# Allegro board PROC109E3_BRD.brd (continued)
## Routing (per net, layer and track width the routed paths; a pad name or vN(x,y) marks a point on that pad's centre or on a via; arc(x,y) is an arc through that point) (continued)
VBAT_XDS: length 4.1
  BOTTOM w0.178: 18.11,30.69 U37.68
  BOTTOM w0.33: 18.11,30.69 17.42,30 C208.1 R249.2
VBUS_DETECT: length 1.7
  TOP w0.135: R113.1 14.12,28.19 U20.4
VBUS_TYPEC: length 6.9
  TOP w0.254: J10.B4 19.77,16.49 J10.A9 19.77,18.71 v1(19.61,18.87) ; C70.1 20.43,19.81 ; J10.B9 17.27,16.49 J10.A4 17.27,18.5 v1(16.73,19.05)
  BOTTOM w0.381: J10.B4 19.72,16.97 ; J10.B9 17.32,16.97
  vias: v1(15.46,20.32) v1(15.46,19.05) v1(16.48,20.35) v1(19.68,23.88) v1(19.68,22.61) v1(19.84,21.59) v1(21.34,22.61)
VBUS_XDS_USB: length 43.5
  TOP w0.203: U24.10 U24.1
  TOP w0.254: 9.73,23.39 9.49,23.16 U24.10 ; v1(9.14,33.12) 8.06,32.04 2.58,32.04 TP27.1
  TOP w0.381: 6.81,22.71 6.48,22.38 J20.1
  BOTTOM w0.33: U38.6 11.57,32.65 ; 10.16,32.51 11.32,31.35 U38.4
  BOTTOM w0.381: R222.2 R219.1
  BOTTOM w0.635: 15.49,43.41 R222.2
  BOTTOM w0.762: 15.49,43.41 14.07,41.99 10.77,41.99 9.37,40.59 9.37,36.68 10.16,35.89 10.16,34.14 v1(9.14,33.12) 9.14,31.37 11.15,29.36 11.15,25.63 v1(9.35,23.83) v1(8.08,23.83)
VCC3V3_TA: length 96.8
  TOP w0.178: 29.54,52.12 29.37,51.95 U4.2 v1(28.57,51.65)
  TOP w0.203: v1(5.08,41.96) 5.49,41.55 TP49.1
  TOP w0.33: U4.1 C5.1 v1(30.96,54.08)
  TOP w0.381: v1(10.4,54.99) v1(10.4,53.11) v1(10.4,51.23) v1(10.4,49.35) v1(10.4,47.47) ; v1(26.39,51.1) 26.39,50.33 R28.2 ; v1(26.37,48.06) 26.37,48.81 R34.2 ; U9.5 4.21,45.81 v1(3.94,46.08) ; U9.8 4.31,43.86 4.01,43.56 v1(4.01,42.6) 4.65,41.96 v1(5.08,41.96)
  TOP w0.508: R17.2 26.39,51.8 v1(26.39,51.1) ; R53.2 R67.2 R70.2 ; R34.2 R28.2
  L03_SIG1 w0.381: v1(4.01,42.6) 3.94,42.67 v1(3.94,46.08) 8.18,46.08 9.58,47.47 v1(10.4,47.47) ; v1(4.01,42.6) 4.45,42.6 v1(5.08,41.96) ; v1(4.01,42.6) 4.01,36.86 v1(6.55,34.32) ; v1(28.57,51.65) 28.02,51.1 v1(26.39,51.1) 19.08,51.1 18.78,51.41 15.29,51.41 14.99,51.1 13.67,51.1 12.85,50.29 12.24,50.29 11.3,49.35 v1(10.4,49.35)
  L04_PWR1 w0.381: v1(7.49,26.03) v1(9.27,26.03) 9.27,27.23 v1(9.3,27.25)
  BOTTOM w0.254: U26.15 23.72,54.76 23.6,54.64 ; 23.75,54.36 23.85,54.26 U26.14 ; C146.1 7.57,35.81 ; C155.1 7.57,34.92
  BOTTOM w0.33: v1(22.53,53.29) 22.43,53.39 C85.1 ; 33.45,52.38 C88.1 U28.5
  BOTTOM w0.381: R209.2 v1(10.4,47.47) ; v1(9.3,27.25) 9.3,26.68 9.27,26.66 v1(9.27,26.03) 8.44,26.03 C243.1 8.33,26.03 v1(7.49,26.03)
  BOTTOM w0.508: R182.1 12.07,54.63 11.71,54.99 v1(10.4,54.99) R178.1 ; R191.2 24.94,49.49 v1(26.37,48.06) ; R202.2 12.07,48.99 11.71,49.35 v1(10.4,49.35) R197.2 ; R187.1 12.07,52.88 11.84,53.11 v1(10.4,53.11) R186.1 ; R196.2 12.07,50.79 11.63,51.23 v1(10.4,51.23) R189.2 ; 33.45,52.38 32.65,52.38 v1(30.96,54.08)
VCC3V3_XDS: length 93.9
  TOP w0.254: R109.2 v1(29.84,31.62) ; v1(27.28,30.1) 27.28,30.61 27.52,30.84 R108.2 ; v1(37.57,19.41) 37.57,18.01 TP35.1 ; C44.1 U16.7
  TOP w0.33: v1(67.85,24.67) 68.12,24.94 68.33,24.94 C60.1 68.44,24.8 68.44,24.49 68.09,24.14 U25.16 ; v1(25.07,34.14) C44.1
  TOP w0.381: v1(37.57,19.41) 40.28,22.12 40.28,32.05 38.86,33.48 ; R99.2 v1(22.05,33.12) ; 25.43,27.86 25.22,27.66 v1(25.22,26.42) ; R100.2 v1(23.52,33.12) ; R98.2 v1(20.5,33.12) ; R101.2 v1(24.99,33.12)
  L05_GND2 w0.381: v1(58.81,21.82) 59.29,22.3 66.52,22.3 67.85,23.64 v1(67.85,24.67)
  BOTTOM w0.178: U37.26 36.08,31.89 C180.1 ; U37.28 35.81,31.09 35.81,31.09 C191.1 ; v1(17.78,39.7) 17.78,39.66 17.96,39.49 U37.90 ; 27.1,44.45 U37.113 ; C121.1 36.67,39.49 U37.7 ; U37.51 25.9,26.9 ; v1(27.28,30.1) 27.55,29.82 27.55,28.95 27.5,28.9 U37.47 ; 30.71,26.77 30.7,26.78 U37.39 ; 35.94,39.19 35.84,39.09 U37.8 ; v1(30.7,42.24) 30.7,42.24 U37.122 ; U37.16 35.75,35.89 35.75,35.89 ; U42.8 C260.1 ; U37.79 17.94,35.09 ; 17.73,31.09 U37.69 ; U37.52 25.5,26.87 25.63,26.75 ; v1(22.02,44.73) 22.3,44.45 U37.101
  BOTTOM w0.254: U38.1 14.39,32.65 14.82,32.65 ; U45.16 36.23,19.02 36.44,18.81 C262.1 v1(37.57,19.41) ; v1(17.04,32.28) 17.04,31.78 17.73,31.09
  BOTTOM w0.33: v1(36.98,35.86) 36.98,35.87 C151.1 36.4,35.89 35.75,35.89 ; 38.44,40.06 v1(36.68,40.06) C121.1 ; v1(17.04,32.28) C181.1 C182.1 15.35,32.97 15.8,33.43 R246.1 ; 17.94,35.09 17.88,35.03 C154.1 16.47,35.03 v1(15.88,34.43) ; 27.1,44.45 26.95,44.6 C104.1 27.51,45.24 v1(27.51,45.24) ; 25.9,26.9 26.09,26.72 C242.1 25.5,26.14 v1(25.22,26.42) ; v1(31.62,26.72) 31.62,26.14 31.45,25.96 C240.1 30.71,26.77 ; v1(58.81,21.82) 58.87,21.88 64.9,21.88 65.2,21.58 C260.1
  BOTTOM w0.381: 38.44,40.06 38.7,40.06 R235.1 ; R249.1 15.35,28.47 15.73,28.09 v1(15.93,28.09)
  vias: v1(14.61,34.43) v1(14.61,33.16) v1(36.14,30.48) v1(36.17,32.72)
VCC_5V0_CAN: length 4.2
  TOP w0.203: v1(165.84,22.66) 164.92,22.66 TP50.1
  BOTTOM w0.254: v1(165.84,22.66) R270.2
  BOTTOM w0.33: U44.3 C257.1 R270.2
VDD_1V1: length 25.7
  TOP w0.254: v1(138.07,42.49) 137.52,42.49 C34.1 137.51,42.89 138.18,43.57 U7.39 ; v1(138.07,23.47) 138.06,23.45 C61.1 137.51,23.92 138.18,24.59 U19.39 ; U19.31 134.78,28.78 134.64,28.64 C56.1 133.98,29.18 133.99,29.18 v1(133.99,29.2) ; C17.1 v1(144.35,47.83) U7.6 ; C55.1 v1(144.35,28.78) U19.6 ; U7.31 134.78,47.83 134.64,47.69 C19.1 133.98,48.23 133.99,48.23 v1(133.99,48.25)
  TOP w0.381: TP30.1 125.19,28.46 v1(125.19,27.25)
  BOTTOM w0.229: 125.6,29.67 125.48,29.79 U39.10 ; 125.73,30.05 125.49,30.29 U39.9
  BOTTOM w0.254: v1(138.07,42.49) 138.02,42.44 C113.1 ; C97.1 133.96,48.23 v1(133.99,48.25)
  BOTTOM w0.33: C229.1 126.19,27.49 ; C96.1 144.34,47.83 v1(144.35,47.83) C17.1 ; C55.1 v1(144.35,28.78) 144.34,28.78 C217.1 ; v1(133.99,29.2) 133.98,29.19 C56.1 134,28.62 C228.1 ; v1(138.07,23.47) 138,23.39 C256.1 ; C98.1 133.96,46.62 C97.1
  BOTTOM w0.508: C222.1 125.7,28.63
  vias: v1(125.19,25.98) v1(126.46,25.98)
VDD_1V1_SS: length 1.7
  BOTTOM w0.203: C183.1 126.1,31.29 U39.7
VDD_1V8: length 84.1
  TOP w0.203: TP5.1 63.58,53.01 40.82,53.01 37.83,55.99 33.24,55.99 32.33,55.09 31.29,55.09 30.73,55.66 29.9,55.66 26.9,52.65 25.21,52.65 24.85,52.3 23.83,52.3 23.55,52.58 22.92,52.58 19.94,49.6 v1(19.94,47.93)
  TOP w0.254: C30.2 76.61,41.94 76.87,41.67 U11.5 ; v1(66.17,51.31) 66.17,50.93 R30.2 65.1,51.19 v1(65.1,51.32) 64.69,51.32 R29.2
  TOP w0.305: U18.F14 79.35,32.4 v2(79.35,32.84)
  TOP w0.33: v1(77.37,42.47) 77.37,42.49 77.04,42.82 C30.2
  TOP w0.381: v1(92.18,30.56) v1(92.99,30.56)
  L03_SIG1 w0.152: v2(79.35,32.84) 78.7,33.49 77.44,33.49 77.33,33.38
  L03_SIG1 w0.254: 77.33,33.38 73.11,33.38 72.71,33.78 71.35,33.78 68.88,31.32 v1(68.3,31.32)
  L03_SIG1 w0.381: v1(66.17,51.31) 65.11,51.31 v1(65.1,51.32)
  L04_PWR1 w0.254: v1(92.18,30.56) 92.04,30.69 92.04,33.94 91.31,34.67
  L04_PWR1 w0.508: v1(77.06,41.05) 77.06,42.16 v1(77.37,42.47)
  BOTTOM w0.135: v1(91.72,28.4) v1(92.99,28.4)
  BOTTOM w0.305: C162.1 78.63,33.36 78.63,33.36 79.15,32.84 v2(79.35,32.84)
  BOTTOM w0.381: R198.1 v1(19.94,47.93) ; FB1.1 77.37,43.22 v1(77.37,42.47) 78.09,41.74 FB2.1
  BOTTOM w0.508: FB2.1 77.14,41.12 v1(77.06,41.05)
  vias: v1(64.9,52.58) v1(66.17,52.58) v1(68.76,25.45)
VDD_1V8_CT: length 3.8
  BOTTOM w0.254: U27.5 17.74,57.82 18.71,58.79 C80.1
VDD_1V8_ENABLE: length 31.4
  TOP w0.254: U10.8 42.79,44.11 v1(42.55,43.87) 39.29,43.87 38.81,44.35 38.81,49.96 41.05,52.2 56.55,52.2 57.07,51.68 R31.1
  BOTTOM w0.381: R224.1 v1(42.55,43.87)
VDD_1V8_R: length 1
  TOP w0.33: 62.61,48.25 U5.1 ; C20.1 64.67,48.36
VDD_1V8_SENSE: length 5.9
  BOTTOM w0.135: U27.10 19.57,53.08 19.94,52.71 R198.2 R199.1
VDD_2V5: length 19.9
  TOP w0.254: C23.1 v1(144.35,46.33) U7.3 ; U19.9 v1(144.35,30.28) C53.1 ; C58.1 v1(144.35,27.28) U19.3 ; C11.1 v1(144.35,49.33) U7.9
  TOP w0.381: v1(125.24,37.97) 125.24,38.77 TP20.1 R81.2
  BOTTOM w0.229: 125.73,40.77 125.49,41.01 U33.9 ; U33.10 125.48,40.51 125.6,40.39
  BOTTOM w0.33: C231.1 144.32,27.25 v1(144.35,27.28) C58.1 144.95,26.78 145.03,26.7 C238.1 144.68,26.03 v1(144.32,25.68) ; C11.1 v1(144.35,49.33) ; C107.1 145.03,45.67 144.91,45.8 144.95,45.84 C23.1 v1(144.35,46.33) 143.8,46.33 C100.1 ; C53.1 v1(144.35,30.28) ; C130.1 126.28,38.21
  BOTTOM w0.381: C107.1 144.6,45.09 v1(144.22,44.7)
  BOTTOM w0.508: C125.1 125.71,39.35 125.7,39.34
  vias: v1(125.24,36.7) v1(126.46,36.7)
VDD_2V5_PG: length 21.5
  TOP w0.203: R81.1 v1(115.7,39.37)
  TOP w0.254: v1(121.34,41.35) 121.99,40.69 R81.1
  BOTTOM w0.203: U33.3 121.49,41.51 v1(121.34,41.35) ; U39.5 121.35,31.79 120.37,32.77 117.98,32.77 115.7,35.05 v1(115.7,39.37)
VDD_2V5_SS: length 1.7
  BOTTOM w0.203: C111.1 126.1,42.01 U33.7
VDD_CORE_0V85: length 122.9
  TOP w0.102: U18.J10 80.89,30.34 81.38,29.86
  TOP w0.152: U18.R12 83.89,31.38 83.41,31.86 ; U18.N10 82.89,30.29 v2(83.37,29.82) 83.89,30.35 U18.R10
  TOP w0.178: v2(80.41,31.9) 80.7,31.59 U18.J12
  TOP w0.254: U18.L9 v2(81.89,29.39) ; v1(57.76,32.38) 57.76,31.78 C49.1 ; v2(85.36,32.9) 85.39,32.94 U18.V16 ; C48.1 56.62,32.26 v1(56.49,32.38) ; TP23.1 56.49,36.58 v1(56.49,34.92)
  TOP w0.305: U18.R9 83.89,29.45 v2(83.94,29.41) 83.45,29.41 U18.P8 ; v2(80.41,29.84) 80.41,29.38 U18.H8 ; U18.F11 79.39,30.42 v2(79.41,30.4) 79.45,30.36 U18.G10 ; v2(81.39,29.84) 81.38,29.86 U18.J9 ; U18.J12 80.94,31.32 v2(81.4,31.32) 81.39,31.31 U18.K11 ; U18.H15 80.37,32.89 v2(79.87,32.89) ; U18.M8 82.85,29.36 v2(82.88,29.39) 82.88,29.85 U18.N9 ; U18.L13 81.5,31.86 v2(81.46,31.9) 81.39,31.97 U18.K14 ; v2(79.91,28.82) 79.89,28.8 U18.G6 U18.G5 ; v2(80.41,30.4) 80.45,30.36 U18.J10 ; U18.R13 83.41,31.86 v2(83.37,31.9) 83.39,31.93 U18.P14 ; v2(82.39,31.9) U18.M14
  TOP w0.508: C62.1 R130.1 v1(51.26,24.51) ; 55.46,32.26 55.08,32.64 R96.1 55.08,34.55 55.33,34.8
  L03_SIG1 w0.254: v1(56.49,34.92) 56.49,39.11 54.97,40.64 39.45,40.64 36.68,43.41 35.51,43.41 31.24,47.68 31.24,52.42 27.55,56.11 v1(23.22,56.11)
  L04_PWR1 w0.102: v2(83.37,31.9) 83.92,31.9 84.4,32.38
  L04_PWR1 w0.254: v1(79.35,22.56) 78.84,22.56 78.26,21.97 72.77,21.97 70.84,23.9 70.84,25.27 69.93,26.19 63.7,26.19 63.37,25.86 52.6,25.86 v1(51.26,24.51)
  L04_PWR1 w0.305: 84.4,32.38 84.73,32.38 85.25,32.9 v2(85.36,32.9)
  BOTTOM w0.254: C187.1 81.56,31.8 v2(81.46,31.9) 81.4,31.9 v2(81.4,31.32)
  BOTTOM w0.305: C211.1 83.84,29.31 v2(83.94,29.41) ; C211.1 83.32,29.77 v2(83.37,29.82) ; C211.1 82.97,29.31 v2(82.88,29.39) 82.8,29.31 C212.1 81.98,29.31 v2(81.89,29.39) ; v2(83.37,31.9) 83.26,31.8 C186.1 82.5,31.8 v2(82.39,31.9) 82.29,31.8 C187.1 ; v2(80.41,30.4) v2(80.41,29.84) 80.47,29.9 C200.1 ; v2(81.46,31.9) 81.36,31.8 C188.1 80.51,31.8 v2(80.41,31.9) ; C214.1 80.15,28.57 v2(79.91,28.82) 79.91,27.89 C227.1 ; C199.1 81.5,29.95 v2(81.39,29.84)
  BOTTOM w0.33: C227.1 79.67,27.89 79.65,27.88 79.65,27.88 79.36,27.59 79.36,27.58 79.2,27.42 79.2,27.15 ; C163.1 79.96,32.98 v2(79.87,32.89) ; v2(80.41,30.4) 80.35,30.34 C201.1 79.47,30.34 v2(79.41,30.4) ; v2(85.36,32.9) 85.36,33.01 C165.1
  BOTTOM w0.381: v1(74.8,35.76) 74.52,36.04 C136.1 74.52,36.47 v1(73.74,36.47) ; v1(79.35,22.56) 79.15,22.75 C255.1 79.91,23.29 v1(80.11,23.09)
  BOTTOM w0.508: v1(23.22,56.11) 22.61,56.72 R176.2 ; C234.1 79.2,27.15
  vias: v1(56.49,33.66) v1(57.76,34.92) v1(57.76,33.66) v1(59.03,34.92) v1(59.03,33.66) v1(59.03,32.38) v1(60.3,34.92) v1(60.3,33.66) v1(60.3,32.38) v1(76.2,35.94) v1(80.14,25.27) v1(80.06,24.28) v1(80.8,22.56)
VDD_CORE_0V85_EN: length 36.4
  TOP w0.254: R127.1 48.68,24.53 48.94,24.78 v1(48.94,25.25)
  TOP w0.381: U5.3 62.91,49.54 63.23,49.87 R29.1 v1(62.41,50.9)
  BOTTOM w0.203: v1(48.94,25.25) 48.94,28.13 49.99,29.18 49.99,31.62 60.19,41.82 60.19,49.7 61.39,50.9 v1(62.41,50.9)
VDD_CORE_0V85_FB: length 4.4
  TOP w0.254: C62.2 R130.2 R124.1 49.64,25.93 49.64,27.37 49.64,27.37 U21.2
VDD_CORE_0V85_H_SENSE: length 5.9
  TOP w0.135: v1(20.47,58.14) 21.3,58.14 R6.1
  BOTTOM w0.135: U27.6 19.5,55.08 19.68,55.26 19.68,57.35 v1(20.47,58.14) 21.28,58.14 R175.2
VDD_CORE_0V85_L_SENSE: length 5.1
  TOP w0.135: R6.2 20.82,57.06 v1(20.47,56.72)
  BOTTOM w0.135: U27.7 19.5,54.58 20.04,55.11 20.04,56.29 v1(20.47,56.72) R176.1
VDD_CORE_0V85_PG: length 62
  TOP w0.254: Q3.3 v1(3.01,32.83) ; R112.1 U21.8
  TOP w0.381: v1(42.8,31.37) 42.8,29.44 43.37,28.87 R112.1
  L03_SIG1 w0.381: v1(42.8,31.37) 41.22,31.37 38.57,34.02 38.57,39.89 36.82,41.64 32.27,41.64 31.5,40.87 27.37,40.87 26.97,41.26 21.53,41.26 21.24,40.98 15.39,40.98 15,41.37 12.72,41.37 7.11,35.76 7.11,33.9 6.6,33.4 3.59,33.4 v1(3.01,32.83)
VDD_CORE_0V85_R: length 3.8
  TOP w0.254: C50.1 53.32,31.73 53.85,32.26
  TOP w0.508: 53.85,32.26 54.1,32.51 R96.2 54.1,34.42 53.72,34.8
VDD_CORE_0V85_SW: length 4.8
  TOP w0.254: 50.56,30.27 50.56,30.14 50.14,29.71 U21.6
  TOP w0.762: 50.56,30.27 L2.1
VDDA_1P8_USB0: length 6.8
  TOP w0.152: U18.U15 84.89,32.79 v2(85.36,32.33)
  TOP w0.254: TP47.1 v1(92.53,33.73)
  BOTTOM w0.127: C177.1 86.69,32.3
  BOTTOM w0.152: v2(85.36,32.33) 85.73,31.95 86.35,31.95 86.69,32.3
  BOTTOM w0.254: FB5.2 90.56,32.57 91.24,33.25 91.62,33.25 92.1,33.73 v1(92.53,33.73)
  BOTTOM w0.33: C176.1 C177.1
VDDA_1V8: length 105.6
  TOP w0.254: TP40.1 34.14,56.69 v1(32.59,56.69)
  TOP w0.305: U18.F18 79.82,34.36 v2(79.85,34.33) ; v2(79.89,32.33) 79.93,32.36 U18.H14
  TOP w0.33: U1.5 31.91,57.94 32.57,57.28 C4.1 v1(32.59,56.69)
  TOP w0.381: R15.2 12.21,52.93 12.59,52.54 v1(12.82,52.54)
  L03_SIG1 w0.381: v1(12.82,52.54) 12.82,54.24 14.73,56.15 21.7,56.15 22.25,56.69 v1(32.59,56.69) 32.59,47.35 34.04,45.9 35.48,45.9 36.09,46.5 37.21,46.5 38.33,45.38 49.84,45.38 50.2,45.02 55.61,45.02 56.98,43.66 71.66,43.66 74.93,40.39 77.55,40.39 78.28,41.12 v1(80.59,41.12) 79.68,40.21 79.68,38.38 v1(79.96,38.1)
  L05_GND2 w0.203: v2(79.85,34.33) 79.85,33.88 80.27,33.46 80.27,32.71 v2(79.89,32.33)
  BOTTOM w0.305: v2(79.85,34.33) 79.69,34.33 79.05,34.97 79.05,35.14 78.7,35.48 C153.1
  BOTTOM w0.33: 79.33,37.81 78.7,37.19 C135.1 C144.1 C153.1 ; 79.4,39.2 C126.1
  BOTTOM w0.381: C126.1 79.33,37.81 79.32,37.81
  BOTTOM w0.508: v1(80.59,41.12) 79.7,41.12 FB2.2 79.69,40.22 79.71,40.21 79.33,39.83 C126.1
VDDA_3P3_USB0: length 12.8
  TOP w0.152: U18.U16 84.89,33.32 v2(84.42,32.85)
  TOP w0.254: v1(89.81,35.84) 90.22,35.84 TP45.1
  L03_SIG1 w0.254: v1(89.81,35.84) 88.9,35.84 86.4,33.34 84.97,33.34 84.48,32.85 v2(84.42,32.85)
  BOTTOM w0.152: C178.1 84.85,33.3 84.42,32.86 v2(84.42,32.85)
  BOTTOM w0.33: C157.1 87.27,34.75 87.59,35.06 C156.1
  BOTTOM w0.508: C156.1 88.84,35.06 89,34.9 FB4.2 89.65,35.67 v1(89.81,35.84)
VDDA_3V3: length 19.1
  TOP w0.102: v2(80.89,32.38) 81.12,32.6 81.13,32.6 U18.K15
  TOP w0.254: TP43.1 70.38,38.92 70.38,37.87 70.79,37.45 v1(70.79,37.44)
  L03_SIG1 w0.152: v1(70.79,37.44) 71.25,36.98 77.29,36.98 79.28,35 79.28,34.23 80.51,33 80.51,32.75 80.88,32.38 v2(80.89,32.38)
  BOTTOM w0.305: C174.1 80.6,32.38 v2(80.89,32.38)
  BOTTOM w0.33: FB3.2 C142.1
  BOTTOM w0.508: FB3.2 71.3,36.49 70.79,37 v1(70.79,37.44)
VDDA_ADC: length 18.9
  TOP w0.203: TP48.1 80.39,41.99 v1(80.39,42.62)
  TOP w0.305: v2(80.41,34.33) 80.41,33.88 U18.H17 U18.G17
  L03_SIG1 w0.381: v2(80.41,34.33) 80.47,34.33 80.9,34.76 80.9,35.63 81.11,35.84 81.11,38.88 80.79,39.2 80.79,39.94 81.45,40.6 81.45,41.56 v1(80.39,42.62)
  BOTTOM w0.203: v2(80.41,34.33) 80.74,34.66 80.74,35.3 80.7,35.34
  BOTTOM w0.254: C147.1 80.56,35.48 80.7,35.34
  BOTTOM w0.33: v1(80.39,42.62) 81.06,42.62 81.39,42.29 81.39,41.97 C116.1 ; C147.1 C148.1
  BOTTOM w0.508: v1(80.39,42.62) 80.24,42.47 79.61,42.47 79.31,42.77 FB1.2 C109.1
VDDA_PLL0: length 13.4
  TOP w0.254: TP41.1 90.22,27.13 v1(91.06,27.13)
  TOP w0.305: U18.N12 83.32,31.36 v2(83.37,31.32)
  L03_SIG1 w0.102: 86.39,30.76 85.75,30.76 85.54,30.55 85.2,30.55 84.84,30.91 83.77,30.91 v2(83.37,31.32)
  L03_SIG1 w0.254: 89.05,30.56 88.06,30.56 87.86,30.76 86.39,30.76
  L03_SIG1 w0.381: 89.05,30.56 v1(89.46,30.56) v1(90.3,30.56)
  BOTTOM w0.254: FB7.2 90.26,29.57 90.95,28.87 90.95,28.72 91.06,28.61 v1(91.06,27.13)
  BOTTOM w0.305: C185.1 v2(83.37,31.32)
  BOTTOM w0.33: C206.1 87.96,29.8 87.95,29.79 C204.1
VDDA_PLL1: length 12.8
  TOP w0.305: U18.G9 79.88,29.84 v2(79.39,29.84)
  TOP w0.381: v1(74.96,27.36) 73.99,26.39 TP44.1
  L03_SIG1 w0.254: v1(74.96,27.36) 77.44,29.84 v2(79.39,29.84)
  BOTTOM w0.254: v1(74.96,27.36) 74.41,26.84 74.41,26.78 74.02,26.38 C236.1 73.52,26.37 73.49,26.4 C241.1 72.17,26.4 72.09,26.31 FB9.2 ; C210.1 79.37,29.84 v2(79.39,29.84)
VDDA_PLL2: length 14.2
  TOP w0.254: TP46.1 72.62,31.22 v1(71.81,31.22)
  TOP w0.381: v2(79.42,31.32) 79.46,31.36 U18.G12
  L03_SIG1 w0.254: v2(79.42,31.32) 79.39,31.32 78.81,31.9 78.25,31.9 78.08,32.07 77.13,32.07 75.87,30.81 72.21,30.81 v1(71.81,31.22)
  BOTTOM w0.33: C194.1 73.76,30.7 73.31,31.15 C193.1 72.5,31.22 v1(71.81,31.22) 71.39,31.22 FB6.2
  BOTTOM w0.356: C184.1 78.87,31.52 79.07,31.32 v2(79.42,31.32)
VDDA_TEMP: length 19.2
  TOP w0.102: U18.G11 79.95,30.86 v2(80.41,31.32)
  TOP w0.254: U18.M11 v2(82.39,30.4) ; TP42.1 v1(71.88,29.34)
  L03_SIG1 w0.152: 77.55,31.71 78.01,31.71 78.25,31.47 78.54,31.47
  L03_SIG1 w0.254: 77.55,31.71 76.09,30.25 72.8,30.25 v1(71.88,29.34) ; v2(82.39,30.4) 81.91,30.89 80.84,30.89 v2(80.41,31.32) 79.98,30.89 79.12,30.89 78.54,31.47
  BOTTOM w0.254: v2(80.41,31.32) 80.37,31.32 80.06,31.62 C190.1
  BOTTOM w0.305: v2(82.39,30.4) 82.55,30.56 C198.1
  BOTTOM w0.33: C225.1 73.39,28.66 73.51,28.78 C224.1
  BOTTOM w0.508: C225.1 72.03,28.66 71.87,28.5 FB8.2
VDDC_1V2_XDS: length 37.8
  TOP w0.254: v1(18.06,37.29) 34.87,37.29 37.47,39.88 37.47,41.17 34.75,43.89 v1(33.86,43.89)
  BOTTOM w0.178: U37.87 18.16,38.29 ; U37.115 27.9,44.48
  BOTTOM w0.33: v1(18.06,37.29) 18.01,37.34 17.98,37.34 C132.1 17.82,38.29 18.16,38.29 ; v1(33.86,43.89) 33.86,44.44 33.14,45.15 C102.1 C105.1 28.1,44.67 27.9,44.48
VDDSHV_3V3: length 55.9
  TOP w0.152: 83.94,33.86 v2(84.39,33.4) ; v2(78.44,29.39) 78.89,29.85 U18.E9 ; v2(81.89,28.82) 82.35,28.36 U18.M6 ; v2(83.85,28.85) 83.85,28.82 U18.P6 ; 78.47,29.36 78.59,29.24 78.59,29.23 78.89,28.93 U18.E7 ; U18.U8 84.41,29.84 v2(84.36,29.84)
  TOP w0.254: v1(84.58,22.48) 84.58,23.09 TP52.1 ; U18.C13 78.33,32.3 78.39,32.3 ; U18.R17 83.94,33.86
  TOP w0.305: v2(82.88,32.9) 82.88,33.35 U18.N16 U18.N17 ; U18.L6 v2(81.89,28.82) ; U18.U8 U18.U7 ; U18.P5 U18.P6 ; v2(78.44,32.9) 78.48,32.86 U18.E15 ; U18.D13 78.39,32.3 v2(78.43,32.33) 78.45,32.36 U18.E14 ; U18.T8 84.39,29.6 84.36,29.63 v2(84.36,29.84) ; U18.T17 v2(84.39,33.4) ; U18.T11 U18.U11 84.89,31.27 v2(84.94,31.32) ; v2(78.44,29.39) 78.47,29.36 U18.E8
  L03_SIG1 w0.33: v1(84.3,38.2) 84.3,37.66 84.64,37.32 84.64,34.32 84.39,34.08 v2(84.39,33.4)
  L04_PWR1 w0.152: v2(84.36,29.84) 84.36,29.27 83.95,28.85 v2(83.85,28.85)
  L04_PWR1 w0.254: v2(84.36,29.84) 84.83,29.84 ; v2(84.39,33.4) 84.84,33.4
  BOTTOM w0.178: v2(83.85,28.85) 83.94,28.85 84.29,29.21 C213.1
  BOTTOM w0.254: C205.1 85.21,31.32 v2(84.94,31.32) ; 84.45,26.25 84.45,26.14 84.46,26.13 ; v2(81.89,28.82) 81.89,28.69 82.25,28.34 82.57,28.34 82.71,28.19 83.54,28.19
  BOTTOM w0.305: C175.1 82.69,33.1 v2(82.88,32.9) 82.88,33.36 83.25,33.73 84.07,33.73 v2(84.39,33.4) 84.39,34.1 C158.1 84.39,34.34 84.39,35.65 C145.1 ; C215.1 81.6,28.52 v2(81.89,28.82) ; C235.1 84.45,26.25 84.45,27.53 83.85,28.13 v2(83.85,28.85) ; v2(84.36,29.84) 85.16,29.84 85.17,29.85 85.27,29.85 C203.1 ; v2(78.44,29.39) 78.44,29.55 C202.1
  BOTTOM w0.33: C145.1 C140.1 ; C140.1 C133.1 84.61,37.89 v1(84.3,38.2) ; C140.1 C141.1 C134.1 84.21,38.2 v1(84.3,38.2) ; v1(84.3,38.2) v1(84.3,39.01)
  BOTTOM w0.381: v2(78.44,32.9) 78.43,32.89 v2(78.43,32.33) 77.53,32.33 77.01,32.85 C167.1
  BOTTOM w0.508: v1(84.58,22.48) 83.85,21.74 76.17,21.74 75.46,22.45 75.46,25.96 76.28,26.77
  vias: v1(85.6,22.48)
VDDSHV_SDIO: length 34.8
  TOP w0.305: v2(81.85,32.9) 81.89,32.95 U18.L16 U18.L17 ; U18.J17 80.94,33.82 v2(81.41,33.82)
  TOP w0.381: R19.2 89.05,50.41 88.67,50.79 v1(88.67,51.64) ; R21.2 93.29,50.41 v1(93.29,50.42)
  L03_SIG1 w0.254: v2(81.41,33.82) 81.41,33.35 v2(81.85,32.9)
  L04_PWR1 w0.381: v1(88.67,51.64) 86.16,51.64 81.38,46.86 v1(81.38,39.67)
  BOTTOM w0.203: C143.1 81.36,35.41 81.05,35.1 81.05,34.54 C160.1
  BOTTOM w0.33: C160.1 81.37,34.21 81.37,34.13 81.41,34.1 v2(81.41,33.82) 81.39,33.79 C172.1 ; v1(81.38,39.67) 81.38,38.62 80.54,37.78 80.54,36.69 C143.1
  BOTTOM w0.381: v1(88.67,51.64) 88.67,51.59 88.65,51.57 R194.2 R193.2 R192.2 92.75,50.96 v1(93.29,50.42)
BOARD_POWER_EN: length 5.2
  TOP w0.254: R84.2 R85.1 42.3,39.53 43.29,40.52 43.29,41.87 43.43,42 U10.1
BOOTMODE0: length 2.1
  TOP w0.135: R39.1 87.12,47.21 v1(87.12,46.51) 87.12,45.83 R55.2
  BOTTOM w0.135: v1(87.12,46.51) 87.13,46.51 R208.2
BOOTMODE0_R: length 47.7
  TOP w0.102: 84.2,36.7 84.2,36.53 83.95,36.27 83.95,35.91 U18.R21
  TOP w0.135: R55.1 87.12,44.84 v1(87.12,43.87) 87.12,41.68 84.78,39.34 84.78,37.71 84.2,37.13 84.2,36.7
  L03_SIG1 w0.121: v1(87.12,43.87) 89.43,41.56 94.14,41.56 94.68,42.1 97.47,42.1 97.92,41.66 99.19,41.66 99.69,42.16 103.38,42.16 105.39,40.15 110.76,40.15 114.55,43.94 114.55,44.68 v1(115.11,45.24)
  BOTTOM w0.135: v1(115.11,45.24) 116.44,46.57 U32.1
BOOTMODE1: length 2
  TOP w0.135: R56.2 88.52,46.52 v1(88.52,46.53) 88.52,46.53 R40.1
  BOTTOM w0.135: R207.2 88.52,46.53 v1(88.52,46.53)
BOOTMODE2: length 3.1
  TOP w0.135: R41.1 91.38,47.21 v1(91.39,47.22)
  BOTTOM w0.135: R215.2 91.33,45.83 90.68,46.48 R206.2 90.72,47.22 v1(91.39,47.22)
BOOTMODE2_R: length 59.8
  TOP w0.102: v2(83.94,34.89) 83.96,34.86 U18.T19
  L03_SIG1 w0.121: v2(83.94,34.89) 83.94,35.6 83.54,35.99 83.54,40.57 85.88,42.9 85.88,44.12 86.23,44.48 87.48,44.48 87.71,44.24 87.71,43.64 88.82,42.53 v1(89.97,42.53) 90.68,41.82 93.86,41.82 94.59,42.55 103.5,42.55 105.65,40.4 110.64,40.4 114.27,44.04 114.27,45.52 114.02,45.77 113.13,45.77 v1(112.57,45.21)
  BOTTOM w0.135: v1(89.97,42.53) 90.6,43.16 90.6,44.12 91.33,44.85 R215.1 ; U32.6 114.61,49.82 112.57,47.78 v1(112.57,45.21)
BOOTMODE3: length 63.3
  TOP w0.135: R42.2 92.82,48.65 92.99,48.82 v1(92.99,48.85) ; U4.21 33.7,50.65 v1(33.71,50.66)
  L03_SIG1 w0.121: v1(92.99,48.85) 91.45,50.39 88.24,50.39 86.58,52.05 82.02,52.05 81.74,51.76 75.74,51.76 75.36,52.14 40.89,52.14 39.22,50.47 33.89,50.47 v1(33.71,50.66)
BOOTMODE4: length 64
  TOP w0.135: v1(35.59,49.68) 34.87,49.68 34.4,50.15 U4.20 ; v1(92.14,45.82) 92.83,45.82 R59.2
  L03_SIG1 w0.121: v1(92.14,45.82) 91.7,45.82 90.5,47.02 90.5,47.79 88.76,49.53 87.41,49.53 86.44,50.5 83.39,50.5 82.78,51.11 75.26,51.11 74.73,51.63 67.2,51.63 65.84,50.27 57.07,50.27 56.4,49.59 36.12,49.59 36.03,49.68 v1(35.59,49.68)
BOOTMODE5: length 61.5
  TOP w0.135: v1(89.92,47.35) 89.92,45.85 R57.2 ; v1(33.71,49.66) 33.7,49.65 U4.19
  L03_SIG1 w0.121: v1(89.92,47.35) 89.33,47.35 88.5,48.18 87.25,48.18 85.47,49.96 83.57,49.96 82.68,50.85 74.9,50.85 74.38,51.38 67.38,51.38 65.89,49.89 57.28,49.89 56.71,49.32 39.49,49.32 39.24,49.07 34.29,49.07 v1(33.71,49.66)
BOOTMODE6: length 61.6
  TOP w0.135: v1(35.66,48.46) 34.97,49.15 32.82,49.15
  L03_SIG1 w0.121: v1(35.66,48.46) 39.01,48.46 39.62,49.06 48.47,49.06 49.06,48.47 55.52,48.47 55.64,48.59 59,48.59 59.87,47.73 64.39,47.73 67.79,51.12 74.07,51.12 74.6,50.6 82.57,50.6 84.86,48.31 85.88,48.31 86.51,47.68 v1(87.84,47.68)
  BOTTOM w0.135: R217.2 87.71,45.8 87.84,45.94 v1(87.84,47.68)
BOOTMODE7: length 62.1
  TOP w0.135: U4.17 34.23,48.65 v1(34.32,48.56)
  L03_SIG1 w0.121: v1(89.43,46.53) 88.8,47.17 86.56,47.17 85.7,48.03 84.78,48.03 82.46,50.34 74.37,50.34 73.85,50.87 68.24,50.87 64.8,47.43 56.08,47.43 55.32,48.18 39.07,48.18 38.71,47.83 35.05,47.83 v1(34.32,48.56)
  BOTTOM w0.135: v1(89.43,46.53) 89.43,46.05 89.21,45.83 R216.2
BOOTMODE8: length 68.7
  TOP w0.135: U4.16 33.91,48.15 34.39,47.68 36.02,47.68 37.08,48.74 v1(37.08,50.01)
  L03_SIG1 w0.121: v1(95.02,45.82) 93.42,45.82 90.6,48.64 90.6,49.21 89.95,49.86 87.44,49.86 85.51,51.79 82.12,51.79 81.84,51.51 75.39,51.51 75.01,51.89 41.09,51.89 39.22,50.01 v1(37.08,50.01)
  BOTTOM w0.135: R214.2 94.3,45.82 v1(95.02,45.82)
BOOTMODE8_R: length 50.6
  TOP w0.102: v2(85.42,33.86) 84.92,34.36 U18.U18
  L03_SIG1 w0.121: v1(115.11,44.12) 110.53,39.54 109.43,39.54 109.04,39.16 107.27,39.16 106.68,39.75 101.98,39.75 101.5,39.27 v1(93.7,39.27) 91.59,39.27 86.18,33.86 v2(85.42,33.86)
  BOTTOM w0.135: R214.1 94.33,44.85 95.02,44.15 95.02,40.59 v1(93.7,39.27) ; v1(115.11,44.12) 114.68,44.55 114.68,47.91 115.5,48.73 117.13,48.73 117.99,47.87 U32.3
BOOTMODE9: length 64.1
  TOP w0.135: v1(90.64,45.82) 91.36,45.82 R58.2 ; v1(34.72,46.91) 33.98,47.65 U4.15
  L03_SIG1 w0.121: v1(90.64,45.82) 85.69,45.82 84.36,47.15 84.36,48.09 82.43,50.02 73.2,50.02 72.63,50.6 68.78,50.6 65.35,47.17 63.78,47.17 62.97,46.36 56.03,46.36 55.32,47.08 43.6,47.08 42.88,47.79 39.23,47.79 38.79,47.35 35.16,47.35 v1(34.72,46.91)
BOOTMODE9_R: length 50.1
  TOP w0.102: 85.02,36.7 85.02,36.4 84.61,36 84.61,35.64 U18.U20
  TOP w0.135: R58.1 v1(91.37,43.87) 90.73,43.23 89.84,43.23 85.6,38.99 85.6,37.28 85.02,36.7
  L03_SIG1 w0.121: v1(113.74,45.24) 113.74,43.87 110.53,40.66 107.42,40.66 104.65,43.43 97.89,43.43 97.38,42.93 94.51,42.93 93.66,42.07 92.27,42.07 91.37,42.97 v1(91.37,43.87)
  BOTTOM w0.135: U32.4 117.8,48.52 117.22,49.1 114.93,49.1 113.17,47.34 113.17,46.25 113.74,45.69 v1(113.74,45.24)
BOOTMODE10: length 2.1
  TOP w0.135: R43.1 94.29,46.52 v1(94.28,46.51) 94.28,46.51 94.29,46.5 R60.2
  BOTTOM w0.135: R205.2 94.31,46.54 v1(94.28,46.51)
BOOTMODE10_R: length 47.6
  TOP w0.102: 86.41,36.7 86.27,36.7 85.71,36.15 85.71,35.68 U18.V20
  TOP w0.135: R60.1 94.28,44.84 v1(94.28,43.87) 94.28,43.05 93.31,42.08 91.81,42.08 90.4,40.67 88.95,40.67 87.45,39.17 87.45,37.74 86.41,36.7
  L03_SIG1 w0.121: v1(113.16,44.12) 113.16,43.65 110.42,40.91 107.68,40.91 104.9,43.69 97.79,43.69 97.78,43.69 97.76,43.69 97.38,43.31 94.84,43.31 v1(94.28,43.87)
  BOTTOM w0.135: v1(113.16,44.12) 113.16,45.67 112.84,45.98 112.84,47.55 114.75,49.45 117.64,49.45 117.92,49.17 U32.5
BOOTMODE11: length 2.1
  TOP w0.135: R61.2 95.81,45.83 v1(95.81,46.51) 95.81,46.52 R44.1
  BOTTOM w0.135: R204.2 95.86,46.57 v1(95.81,46.51)
BOOTMODE12: length 2.1
  TOP w0.135: R62.2 97.34,46.5 v1(97.33,46.51) 97.34,46.51 R45.1
  BOTTOM w0.135: R203.2 97.41,46.58 v1(97.33,46.51)
BOOTMODE14: length 2.6
  TOP w0.135: R588.1 97.21,41.17 v1(96.98,40.94) R586.2
  BOTTOM w0.135: R589.2 96.98,41.85 v1(96.98,40.94)
BOOTMODE15: length 5.1
  TOP w0.135: R590.1 93.31,40.47 93.81,40.98 v1(94.49,40.98) 94.91,40.55 R587.2
  BOTTOM w0.135: v1(94.49,40.98) 93.11,40.98 R590.1
BOOTMODEON: length 4.6
  TOP w0.135: 35.05,50.58 34.51,50.58 33.94,51.15 U4.22 ; 35.05,50.58 R24.2 ; 35.05,50.58 35.05,51.23 35.26,51.44 v1(35.51,51.44)
  BOTTOM w0.135: U28.4 v1(35.51,51.44)
BP_3V3: length 2.8
  TOP w0.508: R163.2 J5.1
BP_5V0: length 2.8
  TOP w0.508: R161.1 J5.2
BP_ADC0_AIN0: length 7.3
  TOP w0.135: J1.3 44.58,14.75 44.58,17.58 43.61,18.54 R143.1
BP_ADC0_AIN1: length 7.4
  TOP w0.135: J1.11 54.74,14.75 54.74,17.09 55.96,18.31 R152.1
BP_ADC0_AIN2: length 4.2
  TOP w0.135: J1.6 45.83,17.78 44.98,18.62 R144.1
BP_ADC0_AIN3: length 4.1
  TOP w0.135: R146.1 47.73,17.85 48.37,17.21 J1.8
BP_ADC0_AIN4: length 4
  TOP w0.135: R148.1 50.47,17.65 50.91,17.21 J1.10
BP_ADC0_AIN5: length 3.9
  TOP w0.135: J1.12 53.45,18.22 53.21,18.45 R150.1
BP_ADC0_AIN6: length 4.9
  TOP w0.135: J1.14 58.7,18.72 R154.1
BP_ADC0_AIN7: length 5
  TOP w0.135: J1.16 61.44,18.92 R156.1
BP_CONN_1_PORZ: length 27
  TOP w0.135: v1(26.26,57.84) 26.26,57.83 R8.1
  L03_SIG1 w0.127: v1(26.26,57.84) 27.76,57.84 29.02,59.09 36.23,59.09 37.66,60.52 49.57,60.52 J2.10
BP_CONN_2_PORZ: length 88.4
  TOP w0.135: v1(34.32,60.1) 34.3,60.09 R2.1
  L03_SIG1 w0.121: v1(34.32,60.1) 36.14,60.1 37.34,61.29 75.11,61.29 80.04,56.36 83.74,56.36 84.65,55.46 97.2,55.46 97.54,55.12 100.33,55.12 101.52,56.31 101.52,58.26 104.6,61.34 112.25,61.34 J6.10
CAP_VDDS0: length 1.1
  TOP w0.381: v2(78.44,30.9) 78.39,30.95 U18.D12
  BOTTOM w0.356: C192.1 78.35,30.82 v2(78.44,30.9)
CAP_VDDS1: length 1.5
  TOP w0.381: v2(82.39,27.9) 82.44,27.86 U18.N5
  BOTTOM w0.381: C233.1 82.39,27.59 v2(82.39,27.9)
CAP_VDDS2: length 1.3
  TOP w0.102: v2(84.36,30.4) 84.61,30.15 84.61,30.12 84.87,29.86 U18.U9
  BOTTOM w0.381: v2(84.36,30.4) 84.18,30.58 C196.1
CAP_VDDS3: length 1
  TOP w0.381: v2(83.86,32.93) 83.86,33.32 U18.R16
  BOTTOM w0.356: v2(83.86,32.93) 83.66,33.12 C173.1
CAP_VDDS4: length 2
  TOP w0.381: v2(83.37,34.33) 83.33,34.36 U18.N18
  BOTTOM w0.254: v2(83.37,34.33) 83.32,34.33 82.93,34.72 82.93,35.12 83.26,35.45 C149.1
CAP_VDDS5: length 2.7
  TOP w0.381: U18.M18 v2(82.39,33.82)
  BOTTOM w0.203: v2(82.39,33.82) 82.39,34.37 82.04,34.73 82.04,35.34 82.16,35.46 C150.1
CAP_VDDS_MCU: length 1.6
  TOP w0.152: U18.D9 78.33,29.86 v2(77.86,29.39)
  BOTTOM w0.33: v2(77.86,29.39) 77.65,29.39 77.24,28.98 C223.1
CORE_0V85_CT: length 2.9
  BOTTOM w0.254: C82.1 15.54,57.71 16.24,57.01 U27.2
CPSW_RGMII1_RD0: length 33.2
  TOP w0.102: v2(84.38,28.24) 84.39,28.23 U18.T5
  L03_SIG1 w0.121: v2(84.38,28.24) 84.38,27.28 85.63,26.03 87.5,26.03 88.37,25.17 101.5,25.17 101.75,24.92 101.75,23.8 101.5,23.55 100.76,23.55 100.63,23.67 v1(100.63,24.18)
  BOTTOM w0.135: v1(100.63,24.18) 100.63,22.94 100.77,22.81 101.19,22.81 101.32,22.94 101.32,24.49 102.01,25.17 102.01,26.01 104.33,28.34 U40.28
CPSW_RGMII1_RD1: length 33.3
  TOP w0.102: 84.13,25.02 84.13,25.26 83.91,25.49 83.91,26.34 U18.R2
  TOP w0.135: 84.13,25.02 84.13,24.97 84.14,24.97 84.14,24.7 86.16,22.68 86.16,21.16 88.26,19.05 100.46,19.05 v1(102.16,20.75)
  BOTTOM w0.135: U40.26 104.71,27.34 101.73,24.36 101.73,21.18 v1(102.16,20.75)
CPSW_RGMII1_RD2: length 33.2
  TOP w0.102: 85.18,25.26 85.17,25.27 85.17,26.08 U18.U2
  TOP w0.114: 85.42,25.02 85.18,25.26
  TOP w0.135: 85.42,25.02 87.33,23.11 87.33,22.38 88.8,20.9 95.73,20.9 95.86,21.04 95.86,21.66 96,21.79 96.27,21.79 96.4,21.66 96.4,21.04 96.54,20.9 96.81,20.9 96.94,21.04 96.94,21.66 97.08,21.79 97.34,21.79 97.48,21.66 97.48,21.04 97.61,20.9 97.88,20.9 98.02,21.04 98.02,21.66 98.15,21.79 98.42,21.79 98.56,21.66 98.56,21.04 98.69,20.9 98.96,20.9 99.09,21.04 99.09,21.66 99.23,21.79 99.5,21.79 99.63,21.66 99.63,21.12 99.77,20.98 100.23,20.98 101.52,22.28 v1(102.16,22.28)
  BOTTOM w0.135: U40.24 105.08,26.34 102.16,23.42 v1(102.16,22.28)
CPSW_RGMII1_RD3: length 33.3
  TOP w0.102: 84.69,25.02 84.69,25.56 U18.T1
  TOP w0.135: 84.69,25.02 84.69,24.96 86.72,22.94 86.72,21.74 88.27,20.19 100.51,20.19 101.57,21.26 104.32,21.26 104.5,21.08 104.5,20.23 104.36,20.09 103.82,20.09 103.68,20.23 v1(103.68,20.75)
  BOTTOM w0.135: U40.22 105.22,25.34 102.92,23.04 102.92,21.51 v1(103.68,20.75)
CPSW_RGMII1_RX_CTL: length 33.1
  TOP w0.102: 87.74,26.03 87.38,26.39 87.38,26.56 87.08,26.86 U18.Y3
  TOP w0.135: 87.74,26.03 89.31,24.46 96.8,24.46 97.76,23.49 108.92,23.49 109.19,23.22 109.19,22.67 108.85,22.33 v1(105.21,22.33)
  BOTTOM w0.135: v1(105.21,22.33) 105.97,22.33 107.75,24.11 U40.20
CPSW_RGMII1_RXC: length 33.4
  TOP w0.102: U18.U1 84.89,25.14 85.01,25.02
  TOP w0.135: v1(105.21,20.75) 106.34,20.75 106.48,20.89 106.48,21.37 106.32,21.53 101.34,21.53 100.3,20.5 88.65,20.5 87.05,22.1 87.05,22.99 85.01,25.02
  BOTTOM w0.135: U40.18 108.75,23.08 106.43,20.75 v1(105.21,20.75)
CPSW_RGMII1_TD0: length 28.7
  TOP w0.102: U18.Y14 86.67,32.64 87.12,32.64 87.22,32.54 87.74,32.54
  TOP w0.135: v1(106.17,36.96) 105.39,36.17 102.72,36.17 102.12,35.58 97.78,35.58 97.76,35.56 97.74,35.56 94.72,32.54 87.74,32.54
  BOTTOM w0.135: v1(106.17,36.96) 107.87,36.96 108.25,36.58 108.25,35.69 108.41,35.53 109.47,35.53 109.6,35.4 109.6,34.9 109.47,34.77 108.89,34.77 108.75,34.63 U40.42
CPSW_RGMII1_TD1: length 15.1
  TOP w0.102: 87.74,33.08 86.68,33.08 U18.Y16
  TOP w0.135: 87.74,33.08 94.37,33.08 97.85,36.56 R596.1
CPSW_RGMII1_TD1_MUX: length 13.5
  TOP w0.135: v1(103.5,36.96) 104.01,36.96 104.14,37.09 104.14,37.94 104.01,38.07 101.3,38.07 100.99,37.77 R597.2
  BOTTOM w0.135: U40.40 107.75,34.48 106.16,36.07 105.26,36.07 105.12,36.2 105.12,36.65 104.99,36.78 104.72,36.78 104.58,36.65 104.58,36.2 104.45,36.07 103.78,36.07 103.5,36.35 v1(103.5,36.96)
CPSW_RGMII1_TD2: length 28.8
  TOP w0.102: U18.U13 v2(84.38,31.34)
  L03_SIG1 w0.121: v2(84.38,31.34) 84.43,31.34 84.79,31.7 86.77,31.7 87.27,32.21 98.02,32.21 99.95,30.28 v1(101.78,30.28)
  BOTTOM w0.135: U40.37 105.72,32.84 103.91,34.65 102.04,34.65 101.78,34.38 v1(101.78,30.28)
CPSW_RGMII1_TD3: length 28.7
  TOP w0.102: 87.74,32.27 86.99,32.27 U18.AA14
  TOP w0.135: v1(102.23,34.16) 102.23,35.17 102.1,35.31 101.22,35.31 101.08,35.17 101.08,34.76 100.95,34.62 100.68,34.62 100.54,34.76 100.54,35.17 100.41,35.31 100.14,35.31 100.01,35.17 100.01,34.76 99.87,34.62 99.6,34.62 99.47,34.76 99.47,35.17 99.33,35.31 99.01,35.31 98.88,35.17 98.88,34.46 98.74,34.32 98.47,34.32 98.34,34.46 98.34,35.17 98.2,35.31 97.89,35.31 97.66,35.08 97.66,34.56 97.53,34.43 97.02,34.43 94.89,32.31 94.87,32.31 94.83,32.27 87.74,32.27
  BOTTOM w0.135: v1(102.23,34.16) 102.23,33.22 102.39,33.07 103.17,33.07 103.31,33.21 103.31,33.55 103.44,33.68 104.36,33.68 104.65,33.39 104.65,32.23 105.04,31.84 U40.35
CPSW_RGMII1_TX_CTL: length 26.4
  TOP w0.102: U18.W16 85.89,32.94 v2(85.93,32.9)
  L03_SIG1 w0.121: v2(85.93,32.9) 86.45,32.9 87.78,34.24 95.79,34.24 95.91,34.36 95.91,35.01 96.03,35.13 96.27,35.13 96.39,35.01 96.39,34.36 96.52,34.24 96.76,34.24 96.88,34.36 96.88,35.01 97,35.13 97.24,35.13 97.36,35.01 97.36,34.36 97.48,34.24 97.72,34.24 97.84,34.36 97.84,35.01 97.96,35.13 98.2,35.13 98.33,35.01 98.33,34.36 98.45,34.24 98.69,34.24 98.81,34.36 98.81,35.01 98.93,35.13 99.17,35.13 99.29,35.01 99.29,33.35 99.49,33.15 100.8,33.15 101.79,32.16 v1(102.23,32.16)
  BOTTOM w0.135: R595.1 102.49,31.39 102.23,31.65 v1(102.23,32.16)
CPSW_RGMII1_TX_CTL_MUX: length 2.2
  BOTTOM w0.135: R595.2 104.86,30.84 U40.33
CPSW_RGMII1_TXC: length 24.9
  L03_SIG1 w0.121: v1(104.71,29.92) 103.88,29.92 103.07,29.11 99.54,29.11 97.51,31.14 96.22,31.14 96.08,31.01 96.08,30.52 95.96,30.4 95.72,30.4 95.6,30.52 95.6,31.12 95.48,31.24 95.24,31.24 95.12,31.12 95.12,30.4 94.99,30.28 94.75,30.28 94.63,30.4 94.63,31.12 94.51,31.24 94.27,31.24 94.15,31.12 94.15,30.4 94.03,30.28 93.79,30.28 93.67,30.4 93.67,30.97 93.55,31.09 91.3,31.09 91.21,31 v1(91.21,30.56)
  BOTTOM w0.135: v1(104.71,29.92) 104.79,29.84 U40.31 ; R287.2 87.87,31.14 90.63,31.14 v1(91.21,30.56)
DEBOUNCE_MCU_RESETZ: length 85.6
  TOP w0.135: C1.1 R1.1 18.53,61.04 18.2,61.38 D1.1 17.7,62.36 18.02,62.68 SW2.1 20.16,62.68 20.78,63.3 22.91,63.3 23.53,62.68 SW2.3 24.72,61.51 26.44,59.79 31.14,59.79 32.13,60.78 63.98,60.78 67.02,57.74 67.02,45.22 66.47,44.68 58.57,44.68 57.73,43.84 57.73,40.69 58.76,39.66 U13.1
DEBOUNCE_SOC_RESET_REQZ: length 73.7
  TOP w0.135: C2.1 28.21,60.81 28.2,60.8 D2.1 v1(27.61,61.77) SW3.1 28.77,62.68 29.36,63.27 31.57,63.27 32.17,62.68 SW3.3 63.38,62.68 67.29,58.77 67.29,45.11 66.55,44.37 61.19,44.37 59.76,42.95 U13.6
  BOTTOM w0.135: Q7.6 26.1,60.62 Q7.8 26.1,59.97 Q7.1 Q7.2 ; Q7.6 Q7.5 ; Q7.6 26.64,61.22 26.82,61.04 R170.1 27.61,61.77 v1(27.61,61.77)
DEBOUNCE_USER_INTN: length 48
  TOP w0.135: D4.1 75.05,11.46 74.48,10.89 SW5.1 73.62,10.12 72.72,9.22 71.04,9.22 70.14,10.12 SW5.3 67.71,10.12 v1(67.46,9.87) 66.72,9.87 C78.1 66.26,9.89 65.98,10.17 R164.1 65.39,10.17 64.82,10.74 64.82,17.96 63.55,19.23 63.55,22.56 60.32,25.79 60.32,30.98 61.03,31.7 61.03,36.44 59.76,37.71 U13.3
  BOTTOM w0.135: v1(67.46,9.87) 67.29,9.7 Q16.2 Q16.1 65.57,10.35 65.25,10.03 Q16.8 64.88,10.35 Q16.6 Q16.5
EEPROM_A1: length 2.3
  TOP w0.135: U17.2 64.04,27.8 64.34,27.51 R121.2
EEPROM_A2: length 2.6
  TOP w0.135: R122.2 65.57,26.8 64.69,27.68 U17.3
EEPROM_WP: length 2.8
  TOP w0.135: R89.1 64.88,36.55 64.65,36.32 64.39,36.32 64.04,35.97 U17.7
EHRPWM0_A: length 75.2
  TOP w0.102: 85.95,36.7 85.39,36.14 U18.V21
  TOP w0.135: R42.1 93.38,47.21 v1(93.52,47.07) 93.52,43.74 92.94,43.15 92.51,43.15 90.4,41.05 88.85,41.05 87.07,39.27 87.07,37.82 85.95,36.7
  L03_SIG1 w0.121: v1(93.52,47.07) 93.52,48.92 91.79,50.65 88.34,50.65 86.53,52.46 80,52.46 79.1,53.36 71.68,53.36 71.3,52.98 69.01,52.98 68.48,53.51 64.59,53.51 63.96,52.88 44.51,52.88 J2.1
EHRPWM0_B: length 78.7
  TOP w0.102: U18.U21 85.09,36.06 85.09,36.19 85.57,36.67 85.57,36.7
  TOP w0.135: R59.1 92.84,44.84 v1(92.84,43.87) 90.4,41.43 88.75,41.43 86.66,39.34 86.66,37.79 85.57,36.7
  L03_SIG1 w0.121: v1(92.84,43.87) 92.84,44.5 93.48,45.14 96.57,45.14 96.97,45.54 96.97,46 96.27,46.7 96.27,47.75 95.15,48.87 95.15,49.35 93.6,50.9 88.45,50.9 86.64,52.71 80.11,52.71 79.2,53.62 71.45,53.62 71.07,53.24 69.12,53.24 68.74,53.62 68.59,53.77 64.48,53.77 63.91,53.19 46.73,53.19 J2.3
EHRPWM0_TZN_IN0: length 87
  BOTTOM w0.135: J2.13 56.84,57.5 56.84,58.11 57.25,58.52 57.25,59.94 57.81,60.5 70.99,60.5 73.63,57.87 82.75,57.87 84.15,59.26 84.15,60.1 86.29,62.24 121.02,62.24 123.29,59.97 123.29,55.91 126.03,53.16 126.03,50.14 125.71,49.82 U32.11
EHRPWM1_A: length 80.4
  TOP w0.102: 84.75,36.7 84.75,36.42 84.39,36.07 U18.T20
  TOP w0.135: R57.1 89.97,44.78 v1(89.97,43.87) 89.65,43.55 89.65,43.45 85.32,39.12 85.32,37.41 84.75,36.85 84.75,36.7
  L03_SIG1 w0.121: v1(89.97,43.87) 89.97,44.18 90.52,44.73 91.78,44.73 92.13,44.38 92.13,43.98 92.66,43.44 93.01,43.44 93.32,43.75 93.32,44.35 93.86,44.89 96.67,44.89 97.76,45.97 97.76,47.57 94.17,51.16 88.56,51.16 86.15,53.56 79.62,53.56 79.31,53.87 71.3,53.87 70.92,53.49 69.24,53.49 68.71,54.02 64.31,54.02 63.74,53.45 49.02,53.45 J2.5
EHRPWM1_B: length 58.6
  TOP w0.102: v2(84.87,33.86) 84.39,34.33 U18.T18
  TOP w0.135: J2.7 50.65,54.36 63.58,54.36 64.21,54.99 v1(66.22,54.99)
  L03_SIG1 w0.121: v2(84.87,33.86) 84.96,33.95 84.96,35.89 85.27,36.2 85.27,41.27 v1(85.8,41.81)
  BOTTOM w0.135: v1(85.8,41.81) 86.87,41.81 87.91,42.85 87.91,44.62 87.71,44.82 R217.1 86.41,44.82 86.16,44.58 78.74,44.58 76.12,47.19 75.59,47.19 67.79,54.99 v1(66.22,54.99)
EHRPWM2_A: length 57.9
  L03_SIG1 w0.121: v1(101.3,53.59) 96.75,53.59 96.24,54.1 90.4,54.1 90.08,53.78 88.54,53.78 87.93,54.38 84.07,54.38 83.42,55.03 78.72,55.03 78.39,54.7 73.47,54.7 72.97,55.19 69.47,55.19 68.94,55.73 65.22,55.73 63.85,54.36 53.19,54.36 J2.9
  BOTTOM w0.135: U30.3 102.06,50.55 101.3,51.31 v1(101.3,53.59)
EHRPWM2_B: length 49.6
  L03_SIG1 w0.121: J2.11 55.48,54.61 63.74,54.61 65.18,56.05 72.53,56.05 73.62,54.95 78.14,54.95 78.47,55.28 83.58,55.28 84.18,54.68 89.26,54.68 v1(89.64,54.31)
  BOTTOM w0.135: v1(89.64,54.31) 91.26,54.31 95.52,50.05 U30.7
EPHY1_XI: length 2.7
  TOP w0.135: R13.2 138.79,52.84 138.79,52.83 v1(138.79,52.82) 139.18,52.43 U7.20
  BOTTOM w0.135: v1(138.79,52.82) 138.79,53.48 R13.2
EQEP1_A: length 24.5
  TOP w0.135: C77.1 157.11,12.67 157.46,12.31 J12.1
  BOTTOM w0.135: U46.16 143.73,9.11 144.32,8.51 157.15,8.51 157.46,8.82 J12.1 157.46,11.22 157.05,11.63 156.82,11.63 156.51,11.94 C77.1
EQEP1_A_LS: length 73.6
  TOP w0.102: 82.18,25.02 82.18,26.07 U18.L2
  TOP w0.135: 82.18,25.02 82.18,20.81 87.07,15.93 v1(90.73,15.93)
  L03_SIG1 w0.121: v1(142.23,10.68) 139.45,13.46 139.45,15.98 138.15,17.27 101.68,17.27 100.86,16.45 91.26,16.45 v1(90.73,15.93)
  BOTTOM w0.135: U46.1 v1(142.23,10.68)
EQEP1_B: length 19.8
  TOP w0.135: v1(145.62,13.03) 145.62,9.65 146.46,8.81 153.7,8.81 J12.2 154.92,11.2 154.79,11.33 C76.1
  BOTTOM w0.135: v1(145.62,13.03) 145.56,12.97 U46.14 ; J12.2 154.92,11.21 154.79,11.34 C76.1
EQEP1_B_LS: length 70.4
  TOP w0.102: v2(82.39,26.82) 82.35,26.86 U18.L3
  L03_SIG1 w0.121: v1(135.56,18.34) 132.51,18.34 131.2,19.65 112.92,19.65 112.45,19.19 97.39,19.19 96.22,18.01 86.73,18.01 85.97,18.77 84.53,18.77 83.74,19.56 83.74,24.05 82.39,25.4 v2(82.39,26.82)
  BOTTOM w0.135: v1(135.56,18.34) 135.56,17.48 140.06,12.97 U46.3
EQEP1_I: length 14.4
  TOP w0.135: C75.1 152.98,11.8 152.38,11.2 J12.3
  BOTTOM w0.135: J12.3 152.38,11.21 152.98,11.81 C75.1 151.8,12.67 150.99,13.47 U46.13
EQEP1_I_LS: length 66.2
  TOP w0.102: v2(83.94,27.38) 83.89,27.44 U18.R5
  L03_SIG1 w0.121: v1(137.44,20.6) 133.12,20.6 132.29,21.43 114.69,21.43 112.85,23.27 98.7,23.27 97.41,24.56 86.76,24.56 v2(83.94,27.38)
  BOTTOM w0.135: v1(137.44,20.6) 137.44,16.03 140,13.47 U46.4
EQEP2_A: length 20.9
  TOP w0.135: C73.1 156.51,18.47 157.46,17.52 J21.1
  BOTTOM w0.135: U46.12 151.41,13.97 152.27,14.83 157.08,14.83 157.46,15.21 J21.1 157.46,18.69 157.13,19.02 C73.1
EQEP2_A_LS: length 121.5
  TOP w0.102: U18.B14 77.11,32.08 76.22,32.08 76.11,32.2 76.05,32.2
  TOP w0.135: v1(68.3,12.52) 67.06,12.52 65.49,14.09 65.49,18.23 64.82,18.9 64.82,22.1 60.86,26.06 60.86,30.48 63.37,32.99 66.96,32.99 68.17,31.78 70.9,31.78 71.32,32.2 76.05,32.2 76.05,32.2
  L03_SIG1 w0.121: v1(68.3,12.52) 71.03,15.25 86.86,15.25 86.9,15.21 86.92,15.21 89.47,12.67 98.84,12.67 100.13,11.38 137.31,11.38 138.67,12.73 138.67,15.87 v1(138.35,16.18)
  BOTTOM w0.135: v1(138.35,16.18) 138.35,15.73 140.11,13.97 U46.5
EQEP2_B: length 16.4
  TOP w0.135: C72.1 154.79,17.68 154.92,17.55 J21.2
  BOTTOM w0.135: C72.1 154.79,16.51 J21.2 153.67,15.14 152.02,15.14 151.35,14.47 U46.11
EQEP2_B_LS: length 94.8
  L03_SIG1 w0.121: v1(140.26,16.94) 138.35,18.85 132.44,18.85 131.37,19.91 112.7,19.91 112.35,19.56 100.07,19.56 97.64,22 v1(93.42,22)
  BOTTOM w0.135: R244.2 71.17,33.73 70.31,32.87 68.17,32.87 67.15,31.85 67.15,24.16 68.32,22.99 71.95,22.99 74.87,20.08 91.5,20.08 v1(93.42,22) ; v1(140.26,16.94) 139.75,16.43 139.75,15.09 140.37,14.47 U46.6
EQEP2_I: length 14
  TOP w0.135: J21.3 152.38,17.55 152.98,18.15 C71.1
  BOTTOM w0.135: U46.10 150.97,14.97 J21.3 152.38,17.56 152.98,18.16 C71.1
EQEP2_I_LS: length 20.8
  TOP w0.135: U22.3 v1(154.58,23.77)
  BOTTOM w0.135: v1(154.58,23.77) 153.49,23.77 147.37,17.65 141.68,17.65 140.18,16.15 140.18,15.34 140.55,14.97 U46.7
FB_1V1: length 3.1
  BOTTOM w0.203: U39.8 125.73,30.79
  BOTTOM w0.381: R248.2 126.32,30.79 125.73,30.79
  BOTTOM w0.508: R248.2 R247.1
FB_2V5: length 3.1
  BOTTOM w0.203: U33.8 125.73,41.51
  BOTTOM w0.381: 125.73,41.51 126.32,41.51 R233.2
  BOTTOM w0.508: R233.2 R232.1
FSI/BP_MUX_SEL: length 35.8
  TOP w0.102: 86.82,36.7 86.57,36.46 86.54,36.46 86.53,36.44 86.29,36.44 85.91,36.06 85.91,35.38 U18.W20
  TOP w0.135: 86.82,36.7 86.82,36.73 87.81,37.72 87.81,39.07 88.98,40.23 90.35,40.23 91.72,41.61 94.03,41.61 95.81,43.38 v1(95.81,43.87) 95.81,44.84 R61.1
  L03_SIG1 w0.121: v1(104.39,44.97) 103.72,44.29 97.16,44.29 96.73,43.87 v1(95.81,43.87)
  BOTTOM w0.135: U30.1 104.44,51.55 104.84,51.14 R190.2 106.42,51.14 106.93,50.62 106.93,47.51 v1(104.39,44.97)
FSI_RX0_CLK: length 27.4
  BOTTOM w0.135: U30.2 102.23,51.05 102.08,51.19 102.08,51.77 102.28,51.96 102.28,57.01 98.39,60.89 88.73,60.89 87.76,59.92 87.76,57.93 J16.1
FSI_RX0_D0: length 11.2
  BOTTOM w0.135: J16.5 91.55,54.4 95.5,50.44 97.72,50.44 97.83,50.55 U30.8
FSI_RX0_D1: length 46.3
  TOP w0.135: v1(122.63,49.12) 122.05,49.71 122.05,52.76 120.62,54.18 109.78,54.18 108.24,52.64 102.35,52.64 v1(101.85,52.14)
  BOTTOM w0.135: U32.12 122.68,49.17 v1(122.63,49.12) ; v1(101.85,52.14) 101.85,56.01 97.24,60.62 93.57,60.62 92.86,59.92 92.86,58.62 93.26,58.23 93.26,57.47 J16.7
FSI_RX0CLK_PWM2A: length 27
  TOP w0.135: v1(104.39,50.62) 106.14,52.37 108.5,52.37 109.8,53.67 119.74,53.67 120.8,52.6 120.8,50.03 v1(122.94,47.9)
  BOTTOM w0.135: v1(104.39,50.62) 104.39,50.23 104.21,50.05 U30.4 ; v1(122.94,47.9) 122.96,47.87 U32.14
FSI_RX0D0_PWM2B: length 50.9
  L03_SIG1 w0.121: v1(92.53,42.57) 92.86,42.57 93.83,43.54 93.83,44.01 94.11,44.29 96.8,44.29 97.05,44.54 100.91,44.54 101.75,45.39 104.57,45.39 107.54,42.42 110.39,42.42 v1(112.19,44.22)
  BOTTOM w0.135: v1(112.19,44.22) 112.95,43.46 118.87,43.46 120.83,45.42 120.83,46.63 122.71,48.52 U32.13 ; U30.6 94.33,49.55 93.07,48.29 93.07,45.24 92.33,44.5 92.33,43.06 v1(92.53,42.57)
FSI_TX0_CLK: length 25.6
  TOP w0.102: U18.P21 83.59,36.06 83.59,36.22 83.87,36.5 83.87,36.7
  TOP w0.135: 83.87,36.7 83.87,39.4 85.29,40.82 85.29,44.22 85.84,44.77 85.84,51.86 87.71,53.72 87.71,57.94 J16.2
FSI_TX0_D0: length 40.7
  TOP w0.102: U18.Y18 87.35,34.36 87.48,34.49 87.48,34.49 87.74,34.75 87.74,34.77
  TOP w0.135: v1(98.78,44.98) 98.93,44.83 98.93,41.93 97.69,40.69 97.69,39.37 97.45,39.13 R586.1 96.98,38.51 96.52,38.05 93.93,38.05 92.89,37.01 89.98,37.01 87.74,34.77
  BOTTOM w0.135: J16.6 92.71,58.02 92.71,57.14 92.72,57.13 92.72,56.16 92.71,56.15 92.71,55.25 95.38,52.58 99.05,52.58 100,51.63 100,49.38 98.35,47.73 98.35,45.41 v1(98.78,44.98)
FSI_TX0_D1: length 36.2
  TOP w0.102: 87.52,35.48 U18.AA19
  TOP w0.114: 87.65,35.62 87.52,35.48
  TOP w0.135: 87.65,35.62 89.6,37.57 92.62,37.57 94.56,39.51 R587.1 95.86,39.51 96.29,39.94 96.29,42.95 96.77,43.43 97.69,43.43 98.25,43.99 98.25,45.77 v1(98.78,46.3)
  BOTTOM w0.135: J16.8 95.38,57.89 95.38,55.5 97.41,53.47 98.6,53.47 100.27,51.8 100.27,49.16 98.78,47.68 v1(98.78,46.3)
GPIO1_0: length 85.7
  TOP w0.102: U18.J3 80.48,26.86 v2(80.41,26.82)
  L03_SIG1 w0.121: v1(80.65,18.43) 79.7,18.43 79.35,18.78 79.35,20.19 79.91,20.75 79.91,22.61 79.64,22.88 79.64,26.05 v2(80.41,26.82)
  BOTTOM w0.135: J2.15 58.53,55.35 55.22,52.04 55.22,42.21 49.76,36.75 49.58,36.75 46.54,33.71 46.54,24.25 51.02,19.77 62.78,19.77 63.42,19.13 63.64,18.91 64.8,18.91 66.59,17.12 73.28,17.12 74.29,18.13 80.36,18.13 v1(80.65,18.43)
GPIO1_1: length 83.1
  TOP w0.102: U18.J4 80.46,27.36 v2(80.41,27.38)
  L03_SIG1 w0.121: v1(79.89,18.93) 80.31,19.36 80.31,22.67 80.78,23.13 80.78,27.02 v2(80.41,27.38)
  BOTTOM w0.135: J2.17 61.07,54.79 57.08,50.81 57.08,42.38 53.02,38.31 53.02,37.53 48.67,33.18 48.67,33.17 48.42,32.92 48.41,32.92 47.67,32.17 47.67,23.88 51.21,20.34 62.97,20.34 63.86,19.45 65.02,19.45 66.8,17.67 72.96,17.67 73.97,18.67 77.98,18.67 78.24,18.93 v1(79.89,18.93)
GPIO1_2: length 77.3
  TOP w0.102: U18.G1 79.89,25.57 79.71,25.38 79.71,25.05
  TOP w0.135: v1(77.67,19.38) 78.56,20.27 78.56,23.4 79.71,24.55 79.71,25.05
  BOTTOM w0.135: J2.19 63.61,55.35 59.88,51.63 59.88,42.03 49.4,31.55 49.4,29.11 48.48,28.18 48.48,24.22 50.44,22.25 70.66,22.25 72.69,20.22 73.77,20.22 74.61,19.38 v1(77.67,19.38)
GPIO1_3: length 93.1
  TOP w0.102: U18.H1 80.39,25.55 80.53,25.42 80.53,25.1
  TOP w0.135: v1(80.37,16.56) 78.83,18.1 78.83,23 79.63,23.8 80.19,23.8 80.53,24.14 80.53,25.1
  BOTTOM w0.135: J2.4 42.04,57.93 42.04,54.84 48.06,48.82 48.06,41.43 45.86,39.23 45.86,35.83 43.84,33.81 43.84,24.24 43.84,23.16 49.71,17.3 64.08,17.3 67.29,14.09 67.63,14.09 75.95,14.09 78.01,16.15 79.96,16.15 v1(80.37,16.56)
GPIO1_4: length 90.2
  TOP w0.102: U18.K2 81.39,26.26 81.11,25.98 81.11,25.75 81.34,25.52 81.34,25.02
  TOP w0.135: 81.34,25.02 81.34,20.31 82.42,19.23 v1(82.42,18.05)
  BOTTOM w0.135: J2.8 47.09,57.91 47.09,51.94 48.59,50.44 48.59,41.13 47.64,40.18 47.64,36.71 44.6,33.68 44.6,24.51 51.28,17.84 64.31,17.84 67.51,14.63 73.26,14.63 75.27,16.64 76.42,16.64 76.95,16.12 77.37,16.12 78.29,17.04 81.42,17.04 v1(82.42,18.05)
GPIO1_5: length 84.9
  TOP w0.102: U18.F2 79.38,26.34 79.38,25.66 79.17,25.45 79.17,25.02
  TOP w0.135: 79.17,25.02 79.17,24.89 77.22,22.94 76.97,22.94 76.73,22.71 76.73,18.36 v1(77.39,17.7)
  BOTTOM w0.135: v1(77.39,17.7) 74.4,17.7 73.55,16.86 66.47,16.86 64.69,18.64 51.72,18.64 46.18,24.18 46.18,33.99 48.77,36.58 48.77,37.06 52.58,40.87 52.58,50.42 57.25,55.09 57.25,57.91 J2.16
GPIO1_6: length 55.6
  TOP w0.102: U18.H2 80.71,26.05 80.71,25.58 80.8,25.49 80.8,25.02
  TOP w0.135: 80.8,25.02 80.8,23.79 80.53,23.52 79.93,23.52 79.63,23.22 79.63,22.93 79.91,22.66 79.91,21.97 79.63,21.69 79.63,19.28 79.46,19.11 79.46,18.76 79.63,18.59 79.63,18.54 81.56,16.61 82.83,16.61 86.38,13.07 98.69,13.07 100.63,11.13 119.69,11.13 J5.15
GPIO1_8: length 107.1
  TOP w0.102: U18.H5 80.35,27.86 79.87,27.38 v2(79.85,27.38)
  L03_SIG1 w0.121: v2(79.85,27.38) 78.77,26.3 78.77,23.06 78.61,22.91 78.61,18.8 79.66,17.75 81.18,17.75 81.71,17.22 97,17.22 98.2,18.42 130.4,18.42 v1(130.73,18.08)
  BOTTOM w0.135: J6.20 128.52,59.18 131.19,56.52 131.19,18.54 v1(130.73,18.08)
GPIO1_12: length 52.6
  TOP w0.102: U18.K1 81.61,25.65 81.61,25.14
  TOP w0.135: v1(86.54,13.89) 86.54,15.7 81.61,20.63 81.61,25.14
  BOTTOM w0.135: J1.9 52.69,11.68 66.09,11.68 67.56,13.16 76.32,13.16 78.49,15.32 85.11,15.32 v1(86.54,13.89)
GPIO1_18: length 37.9
  TOP w0.102: U18.K4 v2(81.39,26.82)
  L03_SIG1 w0.121: v2(81.39,26.82) 81.65,26.56 81.65,19.78 v1(83.39,18.05)
  BOTTOM w0.135: J1.15 59.77,12.22 65.64,12.22 67.18,13.77 76.17,13.77 78.28,15.88 81.22,15.88 v1(83.39,18.05)
GPIO1_19: length 51.3
  TOP w0.102: 79.44,25.07 79.44,25.43 79.58,25.58 79.58,26.05 U18.G2
  TOP w0.135: v1(77.19,16.55) 77.82,17.18 77.82,18.34 77.14,19.02 77.14,21.36 77.65,21.87 77.65,22.87 79.44,24.66 79.44,25.07
  L03_SIG1 w0.121: J5.9 112.88,11.94 100.46,11.94 99.22,13.18 89.74,13.18 87.1,15.83 77.91,15.83 v1(77.19,16.55)
GPIO1_20: length 88
  TOP w0.102: U18.L5 81.44,27.86 v2(81.39,27.9)
  L03_SIG1 w0.121: v2(81.39,27.9) 81.03,27.54 81.03,25.12 81.4,24.76 81.4,19.14 v1(81.41,19.13)
  BOTTOM w0.135: v1(81.41,19.13) 81.09,19.44 78.35,19.44 77.84,18.94 73.83,18.94 72.83,17.94 66.92,17.94 65.08,19.78 63.91,19.78 63.08,20.61 51.32,20.61 47.94,23.99 47.94,28.41 48.82,29.29 48.82,31.83 54.23,37.24 54.23,38.66 57.73,42.16 57.73,44.68 58.53,45.48 58.53,51.55 62.33,55.35 62.33,57.91 J2.20
GPIO1_21: length 52.7
  TOP w0.102: 81.07,25.05 81.07,25.5 80.91,25.66 80.91,26.34 U18.J2
  TOP w0.135: J5.14 118.24,14.75 118.24,12.73 117.12,11.61 100.56,11.61 98.83,13.34 86.49,13.34 80.32,19.51 80.32,22.68 81.07,23.44 81.07,25.05
GPIO1_22: length 47.5
  TOP w0.102: 82.63,25.19 82.39,25.43 U18.M2
  TOP w0.135: J5.16 120.76,17.27 106.28,17.27 105.33,18.21 98.25,18.21 97.74,17.7 85.67,17.7 83.13,20.24 83.13,23.8 82.63,24.31 82.63,25.19
GPIO1_26: length 59.3
  TOP w0.102: U18.F5 v2(79.39,28.32)
  TOP w0.135: v1(106.4,17.95) 122.62,17.95 J5.18
  L03_SIG1 w0.121: v1(106.4,17.95) 101.44,17.95 100.45,16.96 81.51,16.96 80.98,17.49 79.51,17.49 78.26,18.75 78.26,19.99 77.65,20.6 77.65,23.14 78.46,23.95 78.46,26.33 79.39,27.26 v2(79.39,28.32)
GPIO1_31: length 49.6
  TOP w0.102: U18.P1 83.39,25.27 83.58,25.09
  TOP w0.135: 83.58,25.09 83.58,24.5 83.96,24.12 83.96,22.29 87.73,18.52 88.04,18.52 88.04,18.51 124.6,18.51 J5.20
GPIO1_32: length 92.9
  TOP w0.102: 83.85,25.2 83.71,25.33 83.71,26.05 U18.P2
  TOP w0.135: 83.85,25.2 83.85,24.61 85.09,23.37 85.09,21.72 88.02,18.79 88.15,18.79 88.15,18.78 129.14,18.78 v1(129.59,19.23)
  BOTTOM w0.135: J6.17 126.78,54.43 128.68,54.43 130.33,52.77 130.33,24.06 129.13,22.86 129.13,19.68 v1(129.59,19.23)
GPIO1_33: length 84.1
  TOP w0.102: U18.T4 84.92,27.36 v2(84.93,27.35)
  L03_SIG1 w0.121: v1(129.57,22.12) 114.38,22.12 112.95,23.55 107.72,23.55 106.55,24.71 104.34,24.71 102.74,26.31 101.83,26.31 101.45,26.69 89.06,26.69 88,27.75 85.33,27.75 v2(84.93,27.35)
  BOTTOM w0.135: v1(129.57,22.12) 130.6,23.15 130.6,53.14 J6.19
